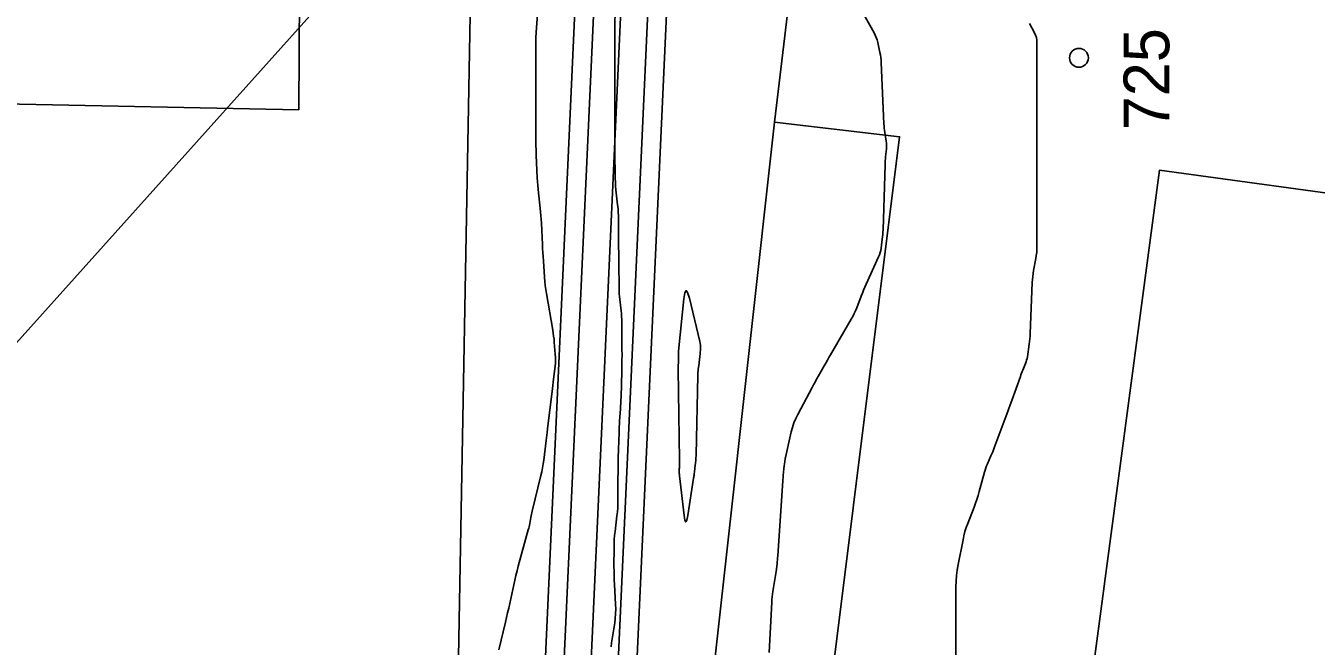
# Model space of a CAD drawing. Extents: x -534481 to -534262, y -1190577 to -1190138.
# Drawn here: x -534356 to -534332.03, y -1190282.16 to -1190270.63 of the extents above; entities that cross this region are included whole.
import ezdxf

# ---------------------------------------------------------------- set-up
doc = ezdxf.new("R2010")
doc.units = 0
for name, color, linetype in [('Bonity', 7, 'Continuous'), ('Definiční body', 7, 'Continuous'), ('Polygon budovy', 7, 'Continuous'), ('Polygon parcely', 7, 'Continuous'), ('Vrstva 18', 7, 'Continuous'), ('Vrstva 19', 7, 'Continuous'), ('Vrstva 31', 7, 'Continuous'), ('Vrstva 32', 7, 'Continuous'), ('Vrstva 46', 7, 'Continuous')]:
    doc.layers.add(name, color=color, linetype=linetype)

msp = doc.modelspace()

# ---------------------------------------------------------------- linework, layer by layer
at = {"layer": 'Bonity'}
msp.add_lwpolyline([(-534409.868, -1190391.439), (-534405.947, -1190382.816), (-534400.873, -1190377.487), (-534393.696, -1190372.718), (-534384.927, -1190365.477), (-534382.631, -1190361.148), (-534355.894, -1190347.823), (-534351.738, -1190342.389), (-534351.577, -1190328.316), (-534347.204, -1190300.921), (-534345.553, -1190283.64), (-534344.682, -1190264.494)], dxfattribs=at)
at = {"layer": 'Definiční body'}
msp.add_line((-534348.02, -1190285.43), (-534347.63, -1190264.06), dxfattribs=at)
msp.add_lwpolyline([(-534341.18, -1190264.8), (-534342.09, -1190272.42), (-534345.3, -1190301.34), (-534346.16, -1190306.72)], dxfattribs=at)
at = {"layer": 'Polygon parcely'}
msp.add_lwpolyline([(-534366.14, -1190271.54), (-534367.96, -1190291.63), (-534363.08, -1190291.98), (-534362.74, -1190289.52), (-534362.49, -1190289.56), (-534361.74, -1190280.34), (-534361.6, -1190280.35), (-534360.7, -1190271.99), (-534350.93, -1190272.19), (-534350.88, -1190263.57), (-534365.11, -1190263.3)], close=True, dxfattribs=at)
msp.add_lwpolyline([(-534334.434, -1190265.214), (-534341.12, -1190264.34), (-534341.18, -1190264.8), (-534342.09, -1190272.42), (-534339.77, -1190272.69), (-534343.2, -1190300.17), (-534333.12, -1190301.37), (-534332.25, -1190294.85), (-534337.72, -1190294.22), (-534334.94, -1190273.31), (-534329.83, -1190274.01), (-534329.03, -1190265.92), (-534330.011, -1190265.792)], dxfattribs=at)
at = {"layer": 'Vrstva 18'}
for points in [[(-534342.189, -1190282.277), (-534342.144, -1190281.341), (-534342.141, -1190281.291), (-534342.136, -1190281.241), (-534342.13, -1190281.191), (-534342.122, -1190281.142), (-534342.084, -1190280.917), (-534342.078, -1190280.881), (-534342.072, -1190280.844), (-534342.067, -1190280.808), (-534342.062, -1190280.771), (-534342.045, -1190280.625), (-534342.041, -1190280.588), (-534342.037, -1190280.551), (-534342.034, -1190280.514), (-534342.031, -1190280.478), (-534341.938, -1190279.084), (-534341.936, -1190279.06), (-534341.934, -1190279.036), (-534341.932, -1190279.012), (-534341.93, -1190278.988), (-534341.916, -1190278.864), (-534341.91, -1190278.806), (-534341.901, -1190278.729), (-534341.899, -1190278.71), (-534341.896, -1190278.691), (-534341.892, -1190278.672), (-534341.888, -1190278.653), (-534341.782, -1190278.176), (-534341.76, -1190278.091), (-534341.732, -1190278.008), (-534341.699, -1190277.928), (-534341.66, -1190277.849), (-534341.394, -1190277.35), (-534341.367, -1190277.299), (-534341.339, -1190277.248), (-534341.311, -1190277.197), (-534341.283, -1190277.147), (-534341.169, -1190276.945), (-534341.14, -1190276.895), (-534341.111, -1190276.845), (-534341.082, -1190276.795), (-534341.053, -1190276.744), (-534340.667, -1190276.082), (-534340.638, -1190276.031), (-534340.612, -1190275.978), (-534340.587, -1190275.925), (-534340.565, -1190275.87), (-534340.481, -1190275.65), (-534340.459, -1190275.595), (-534340.437, -1190275.54), (-534340.414, -1190275.486), (-534340.39, -1190275.432), (-534340.158, -1190274.922), (-534340.142, -1190274.883), (-534340.129, -1190274.843), (-534340.119, -1190274.802), (-534340.112, -1190274.76), (-534340.09, -1190274.592), (-534340.085, -1190274.55), (-534340.081, -1190274.508), (-534340.079, -1190274.466), (-534340.077, -1190274.423), (-534340.039, -1190273.212), (-534340.038, -1190273.175), (-534340.035, -1190273.138), (-534340.033, -1190273.102), (-534340.029, -1190273.065), (-534340.013, -1190272.918), (-534340.01, -1190272.881), (-534340.01, -1190272.845), (-534340.012, -1190272.808), (-534340.017, -1190272.772), (-534340.043, -1190272.61), (-534340.049, -1190272.57), (-534340.054, -1190272.531), (-534340.057, -1190272.492), (-534340.06, -1190272.452), (-534340.109, -1190271.309), (-534340.112, -1190271.262), (-534340.117, -1190271.215), (-534340.125, -1190271.169), (-534340.134, -1190271.122), (-534340.175, -1190270.937), (-534340.186, -1190270.891), (-534340.201, -1190270.847), (-534340.22, -1190270.804), (-534340.241, -1190270.762), (-534340.747, -1190269.853)], [(-534345.052, -1190270.302), (-534345.056, -1190270.671), (-534345.056, -1190270.758), (-534345.057, -1190270.845), (-534345.057, -1190270.931), (-534345.057, -1190271.018), (-534345.057, -1190272.672), (-534345.057, -1190272.758), (-534345.057, -1190272.844), (-534345.057, -1190272.931), (-534345.056, -1190273.017), (-534345.053, -1190273.396), (-534345.052, -1190273.466), (-534345.048, -1190273.535), (-534345.043, -1190273.605), (-534345.037, -1190273.675), (-534345.006, -1190273.953), (-534344.999, -1190274.023), (-534344.994, -1190274.093), (-534344.991, -1190274.162), (-534344.99, -1190274.232), (-534344.987, -1190274.656), (-534344.987, -1190274.75), (-534344.986, -1190274.844), (-534344.985, -1190274.939), (-534344.984, -1190275.033), (-534344.98, -1190275.502), (-534344.979, -1190275.555), (-534344.977, -1190275.608), (-534344.973, -1190275.661), (-534344.967, -1190275.714), (-534344.942, -1190275.925), (-534344.937, -1190275.978), (-534344.933, -1190276.031), (-534344.93, -1190276.084), (-534344.929, -1190276.138), (-534344.926, -1190276.645), (-534344.925, -1190276.745), (-534344.926, -1190276.844), (-534344.927, -1190276.944), (-534344.93, -1190277.044), (-534344.943, -1190277.532), (-534344.945, -1190277.587), (-534344.947, -1190277.642), (-534344.95, -1190277.696), (-534344.954, -1190277.751), (-534344.969, -1190277.969), (-534344.973, -1190278.023), (-534344.976, -1190278.078), (-534344.978, -1190278.133), (-534344.98, -1190278.187), (-534344.994, -1190278.659), (-534344.996, -1190278.752), (-534344.998, -1190278.845), (-534344.999, -1190278.937), (-534345, -1190279.03), (-534345.001, -1190279.439), (-534345.002, -1190279.513), (-534345.005, -1190279.586), (-534345.011, -1190279.66), (-534345.019, -1190279.733), (-534345.054, -1190280.027), (-534345.062, -1190280.1), (-534345.068, -1190280.174), (-534345.071, -1190280.248), (-534345.073, -1190280.322), (-534345.074, -1190280.677), (-534345.073, -1190280.761), (-534345.072, -1190280.844), (-534345.069, -1190280.928), (-534345.065, -1190281.012), (-534345.044, -1190281.379), (-534345.041, -1190281.466), (-534345.043, -1190281.553), (-534345.05, -1190281.64), (-534345.061, -1190281.726), (-534345.12, -1190282.096), (-534345.129, -1190282.17)]]:
    msp.add_lwpolyline(points, dxfattribs=at)
at = {"layer": 'Vrstva 19'}
for points in [[(-534347.215, -1190282.223), (-534347.09, -1190281.712), (-534347.07, -1190281.626), (-534347.05, -1190281.539), (-534347.03, -1190281.452), (-534347.011, -1190281.366), (-534346.936, -1190281.018), (-534346.917, -1190280.932), (-534346.896, -1190280.845), (-534346.875, -1190280.759), (-534346.852, -1190280.673), (-534346.665, -1190279.996), (-534346.657, -1190279.967), (-534346.65, -1190279.938), (-534346.644, -1190279.909), (-534346.638, -1190279.88), (-534346.616, -1190279.764), (-534346.61, -1190279.735), (-534346.604, -1190279.706), (-534346.597, -1190279.677), (-534346.591, -1190279.648), (-534346.431, -1190278.987), (-534346.415, -1190278.916), (-534346.401, -1190278.844), (-534346.389, -1190278.771), (-534346.379, -1190278.699), (-534346.335, -1190278.334), (-534346.317, -1190278.189), (-534346.309, -1190278.116), (-534346.219, -1190277.371), (-534346.197, -1190277.196), (-534346.168, -1190276.956), (-534346.163, -1190276.9), (-534346.161, -1190276.844), (-534346.161, -1190276.788), (-534346.164, -1190276.732), (-534346.183, -1190276.508), (-534346.188, -1190276.452), (-534346.195, -1190276.396), (-534346.202, -1190276.34), (-534346.211, -1190276.284), (-534346.328, -1190275.606), (-534346.34, -1190275.53), (-534346.35, -1190275.455), (-534346.358, -1190275.379), (-534346.364, -1190275.302), (-534346.385, -1190274.997), (-534346.39, -1190274.921), (-534346.395, -1190274.844), (-534346.399, -1190274.768), (-534346.403, -1190274.692), (-534346.423, -1190274.299), (-534346.427, -1190274.228), (-534346.433, -1190274.157), (-534346.439, -1190274.087), (-534346.446, -1190274.016), (-534346.477, -1190273.735), (-534346.484, -1190273.664), (-534346.49, -1190273.594), (-534346.495, -1190273.523), (-534346.499, -1190273.453), (-534346.518, -1190273.032), (-534346.522, -1190272.938), (-534346.524, -1190272.844), (-534346.526, -1190272.751), (-534346.527, -1190272.657), (-534346.527, -1190271.027), (-534346.526, -1190270.936), (-534346.523, -1190270.845), (-534346.519, -1190270.754), (-534346.512, -1190270.663), (-534346.481, -1190270.256)], [(-534337.355, -1190270.588), (-534337.263, -1190270.759), (-534337.243, -1190270.803), (-534337.228, -1190270.847), (-534337.22, -1190270.894), (-534337.217, -1190270.942), (-534337.217, -1190274.732), (-534337.218, -1190274.788), (-534337.222, -1190274.844), (-534337.229, -1190274.9), (-534337.238, -1190274.955), (-534337.28, -1190275.176), (-534337.29, -1190275.231), (-534337.297, -1190275.286), (-534337.303, -1190275.342), (-534337.306, -1190275.398), (-534337.343, -1190276.348), (-534337.345, -1190276.398), (-534337.349, -1190276.448), (-534337.355, -1190276.497), (-534337.361, -1190276.547), (-534337.396, -1190276.78), (-534337.402, -1190276.812), (-534337.409, -1190276.843), (-534337.419, -1190276.874), (-534337.43, -1190276.905), (-534337.479, -1190277.025), (-534337.491, -1190277.055), (-534337.502, -1190277.085), (-534337.514, -1190277.115), (-534337.525, -1190277.146), (-534337.683, -1190277.591), (-534337.713, -1190277.675), (-534337.744, -1190277.76), (-534337.775, -1190277.844), (-534337.806, -1190277.928), (-534338.011, -1190278.473), (-534338.025, -1190278.511), (-534338.04, -1190278.548), (-534338.056, -1190278.585), (-534338.072, -1190278.623), (-534338.137, -1190278.771), (-534338.152, -1190278.808), (-534338.166, -1190278.845), (-534338.179, -1190278.884), (-534338.191, -1190278.922), (-534338.289, -1190279.284), (-534338.31, -1190279.357), (-534338.333, -1190279.43), (-534338.358, -1190279.501), (-534338.384, -1190279.573), (-534338.503, -1190279.878), (-534338.53, -1190279.953), (-534338.554, -1190280.029), (-534338.574, -1190280.106), (-534338.591, -1190280.184), (-534338.682, -1190280.64), (-534338.7, -1190280.743), (-534338.713, -1190280.846), (-534338.721, -1190280.949), (-534338.723, -1190281.053), (-534338.723, -1190282.628)]]:
    msp.add_lwpolyline(points, dxfattribs=at)
msp.add_lwpolyline([(-534343.574, -1190278.864), (-534343.572, -1190278.845), (-534343.568, -1190278.806), (-534343.556, -1190278.7), (-534343.554, -1190278.676), (-534343.552, -1190278.652), (-534343.55, -1190278.628), (-534343.55, -1190278.604), (-534343.518, -1190277.128), (-534343.517, -1190277.1), (-534343.515, -1190277.071), (-534343.512, -1190277.043), (-534343.509, -1190277.014), (-534343.493, -1190276.901), (-534343.49, -1190276.873), (-534343.486, -1190276.844), (-534343.484, -1190276.816), (-534343.481, -1190276.787), (-534343.469, -1190276.635), (-534343.468, -1190276.6), (-534343.469, -1190276.566), (-534343.474, -1190276.531), (-534343.48, -1190276.497), (-534343.673, -1190275.693), (-534343.706, -1190275.585), (-534343.733, -1190275.55), (-534343.756, -1190275.588), (-534343.774, -1190275.7), (-534343.873, -1190276.677), (-534343.875, -1190276.694), (-534343.876, -1190276.711), (-534343.877, -1190276.727), (-534343.877, -1190276.744), (-534343.876, -1190276.811), (-534343.876, -1190276.828), (-534343.876, -1190276.844), (-534343.877, -1190276.861), (-534343.877, -1190276.878), (-534343.879, -1190276.947), (-534343.879, -1190276.964), (-534343.879, -1190276.981), (-534343.879, -1190276.998), (-534343.879, -1190277.015), (-534343.858, -1190278.702), (-534343.857, -1190278.716), (-534343.858, -1190278.73), (-534343.858, -1190278.745), (-534343.858, -1190278.759), (-534343.86, -1190278.816), (-534343.86, -1190278.83), (-534343.86, -1190278.845), (-534343.861, -1190278.859), (-534343.861, -1190278.873), (-534343.861, -1190278.933), (-534343.861, -1190278.947), (-534343.86, -1190278.962), (-534343.859, -1190278.977), (-534343.857, -1190278.991), (-534343.772, -1190279.726), (-534343.757, -1190279.818), (-534343.741, -1190279.848), (-534343.723, -1190279.818), (-534343.704, -1190279.727), (-534343.595, -1190279.037), (-534343.592, -1190279.018), (-534343.589, -1190278.999), (-534343.587, -1190278.98), (-534343.585, -1190278.96)], close=True, dxfattribs=at)
at = {"layer": 'Vrstva 31'}
msp.add_lwpolyline([(-534409.732, -1190388.64), (-534397.101, -1190322.153), (-534346.296, -1190265.502)], dxfattribs=at)
at = {"layer": 'Vrstva 32'}
for points in [[(-534409.97, -1190389.61), (-534406.662, -1190382.333), (-534401.423, -1190376.832), (-534394.204, -1190372.034), (-534385.599, -1190364.929), (-534383.254, -1190360.509), (-534356.45, -1190347.15), (-534352.584, -1190342.096), (-534352.426, -1190328.244), (-534348.048, -1190300.813), (-534346.401, -1190283.581), (-534345.607, -1190266.12)], [(-534409.916, -1190390.337), (-534406.368, -1190382.532), (-534401.196, -1190377.102), (-534393.995, -1190372.316), (-534385.322, -1190365.155), (-534382.997, -1190360.772), (-534356.221, -1190347.427), (-534352.236, -1190342.217), (-534352.076, -1190328.274), (-534347.7, -1190300.857), (-534346.052, -1190283.605), (-534345.255, -1190266.096)], [(-534409.363, -1190391.537), (-534405.527, -1190383.099), (-534400.549, -1190377.873), (-534393.398, -1190373.12), (-534384.532, -1190365.799), (-534382.264, -1190361.524), (-534355.568, -1190348.219), (-534351.24, -1190342.56), (-534351.077, -1190328.359), (-534346.708, -1190300.984), (-534345.054, -1190283.675), (-534344.256, -1190266.142)], [(-534409.02, -1190391.627), (-534405.233, -1190383.298), (-534400.323, -1190378.142), (-534393.189, -1190373.401), (-534384.256, -1190366.025), (-534382.008, -1190361.787), (-534355.339, -1190348.496), (-534350.891, -1190342.681), (-534350.728, -1190328.388), (-534346.36, -1190301.028), (-534344.705, -1190283.7), (-534343.908, -1190266.201)]]:
    msp.add_lwpolyline(points, dxfattribs=at)
at = {"layer": 'Vrstva 46'}
msp.add_circle((-534336.437, -1190271.223), 0.175, dxfattribs=at)

# ---------------------------------------------------------------- texts
at = {"layer": 'Polygon budovy'}
msp.add_text('725', height=0.85, rotation=90, dxfattribs=at).set_placement((-534334.759, -1190272.57))

doc.saveas('drawing.dxf')
